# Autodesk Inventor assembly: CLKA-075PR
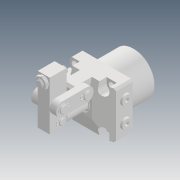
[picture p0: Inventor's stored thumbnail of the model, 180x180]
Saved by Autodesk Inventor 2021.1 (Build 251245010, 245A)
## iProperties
Created: 2018-07
Part Number: CLKA-075PR
Description: STEP AP203
Document SubType Name: Assembly
Designer: user
Title: CLKA-075P-R.STEP
Revision Number: ÈÎºÎ
Sending System: SolidWorks 2015
Preprocessor: SwSTEP 2.0
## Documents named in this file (11)
- D:\Vault_2016\Projekty\Clamptek\Hydraulic\CLKA-P\Inventor\CLKA-075PR\CLKA-075PR.iam
- D:\Vault_2016\Projekty\Clamptek\Hydraulic\CLKA-P\Inventor\CLKA-075PR\CLKA-75P-R-benti.ipt
- D:\Vault_2016\Projekty\Clamptek\Hydraulic\CLKA-P\Inventor\CLKA-075PR\dangjuan01.ipt
- D:\Vault_2016\Projekty\Clamptek\Hydraulic\CLKA-P\Inventor\CLKA-075PR\dangjuan75.ipt
- D:\Vault_2016\Projekty\Clamptek\Hydraulic\CLKA-P\Inventor\CLKA-075PR\duanxiao75.ipt
- D:\Vault_2016\Projekty\Clamptek\Hydraulic\CLKA-P\Inventor\CLKA-075PR\liangan75.ipt
- D:\Vault_2016\Projekty\Clamptek\Hydraulic\CLKA-P\Inventor\CLKA-075PR\luosi75.ipt
- D:\Vault_2016\Projekty\Clamptek\Hydraulic\CLKA-P\Inventor\CLKA-075PR\m12luomo.ipt
- D:\Vault_2016\Projekty\Clamptek\Hydraulic\CLKA-P\Inventor\CLKA-075PR\yabi75.ipt
- D:\Vault_2016\Projekty\Clamptek\Hydraulic\CLKA-P\Inventor\CLKA-075PR\zhangxiao75.ipt
- D:\Vault_2016\Projekty\Clamptek\Hydraulic\CLKA-P\Inventor\CLKA-075PR\¶ÂÍ·G4-1.ipt
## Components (17 placed, 17 different names)
1. CLKA-75P-R-benti_1
2. dangjuan01_2
3. dangjuan75_3
4. duanxiao75_4
5. liangan75_5
6. luosi75_6
7. m12luomo_7
8. yabi75_8
9. zhangxiao75_9
10. liangan75_10
11. zhangxiao75_11
12. dangjuan75_12
13. dangjuan75_13
14. dangjuan75_14
15. dangjuan01_15
16. ¶ÂÍ·G4-1_16
17. ¶ÂÍ·G4-1_17
